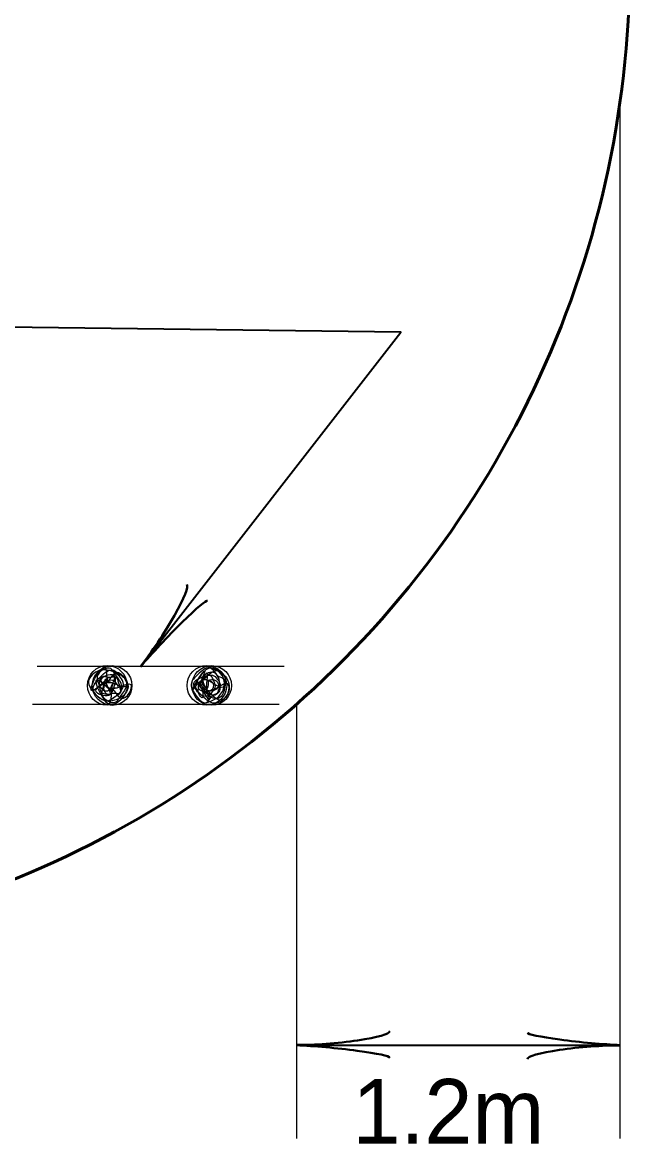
# Model space of a CAD drawing. Extents: x -198 to 658, y -402 to 142.
# Drawn here: x 390.19 to 412.76, y -116.61 to -74.95 of the extents above; entities that cross this region are included whole.
import ezdxf
from ezdxf.enums import TextEntityAlignment as Align

# ---------------------------------------------------------------- set-up
doc = ezdxf.new("R2010")
doc.units = 0
doc.header["$LTSCALE"] = 0.96
doc.layers.add('1', color=7, linetype='Continuous', lineweight=35)
doc.layers.add('4', color=7, linetype='Continuous', lineweight=25)

msp = doc.modelspace()

# ---------------------------------------------------------------- linework, layer by layer
at = {"layer": '1', "lineweight": 25}
for p, q in [((412.4134, -116.4304), (412.4134, -77.8663)), ((399.9154, -98.8829), (390.7354, -98.883)), ((399.736, -100.298), (390.556, -100.2979)), ((400.3925, -116.4304), (400.3925, -100.2786))]:
    msp.add_line(p, q, dxfattribs=at)
at = {"layer": '1'}
msp.add_line((400.3925, -112.9574), (412.4134, -112.9574), dxfattribs=at)
msp.add_lwpolyline([(394.5867, -98.883), (404.2583, -86.4576), (389.5755, -86.274)], dxfattribs=at)
at = {"layer": '1', "lineweight": 53}
msp.add_arc((376.0959, -72.8171), 36.6668, 269.84467, 11.96498, dxfattribs=at)
at = {"layer": '1', "lineweight": 40}
for centre, major_axis, ratio, start_param, end_param in [((395.1294, -97.646), (-1.1683, -1.8061), 0.122415, 0.8963533, 3.1415927), ((395.613, -97.9779), (-1.461, -1.5338), 0.07063, 3.1407148, 5.41811), ((401.7019, -112.6258), (-2.1428, -0.1874), 0.122415, 0.8963533, 3.1415927), ((411.0688, -112.7035), (2.1077, -0.2108), 0.07063, 3.1407148, 5.41811), ((401.7371, -113.2113), (-2.1077, 0.2108), 0.07063, 3.1407148, 5.41811), ((411.104, -113.289), (2.1428, 0.1874), 0.122415, 0.8963533, 3.1415927)]:
    msp.add_ellipse(centre, major_axis=major_axis, ratio=ratio, start_param=start_param, end_param=end_param, dxfattribs=at)
at = {"layer": '1', "lineweight": 25}
for points in [[(393.4, -100.154), (393.76, -99.902), (393.94, -99.542), (393.832, -99.29), (393.436, -99.038), (393.04, -99.038), (392.6439, -99.434), (392.896, -99.902), (393.4, -100.154), (393.616, -100.0099), (393.796, -99.902), (393.868, -99.578), (393.616, -99.146), (393.472, -98.966), (392.968, -99.254), (393.04, -99.614), (393.112, -99.83), (393.256, -99.902), (393.472, -99.902), (393.58, -99.686), (393.616, -99.29), (393.364, -99.29), (393.184, -99.254), (393.04, -99.47), (393.292, -99.794), (393.508, -99.65), (393.5439, -99.506), (393.292, -99.47), (393.328, -99.3979), (392.788, -99.794), (393.256, -98.93), (393.3641, -99.434), (393.6881, -99.11), (394.048, -99.614), (393.292, -99.47), (393.436, -99.938), (392.932, -99.83), (393.292, -99.47)], [(393.5794, -99.0269), (393.9394, -99.2789), (394.1194, -99.6389), (394.0114, -99.8909), (393.6154, -100.1429), (393.2194, -100.1429), (392.8233, -99.7469), (393.0754, -99.2789), (393.5794, -99.0269), (393.7954, -99.171), (393.9754, -99.2789), (394.0474, -99.6029), (393.7954, -100.0349), (393.6514, -100.2149), (393.1474, -99.9269), (393.2194, -99.5669), (393.2914, -99.3509), (393.4354, -99.2789), (393.6514, -99.2789), (393.7594, -99.4949), (393.7954, -99.8909), (393.5434, -99.8909), (393.3634, -99.9269), (393.2194, -99.7109), (393.4714, -99.3869), (393.6874, -99.5309), (393.7233, -99.6749), (393.4714, -99.7109), (393.5074, -99.783), (392.9674, -99.3869), (393.4354, -100.2509), (393.5435, -99.7469), (393.8675, -100.0709), (394.2274, -99.5669), (393.4714, -99.7109), (393.6154, -99.2429), (393.1114, -99.3509), (393.4714, -99.7109)], [(397.036, -100.226), (397.432, -100.046), (397.684, -99.65), (397.612, -99.218), (397.144, -98.93), (396.712, -99.1821), (396.46, -99.542), (396.532, -99.794), (397.036, -100.226), (397.288, -99.938), (397.504, -99.83), (397.54, -99.614), (397.2879, -99.11), (397.036, -99.146), (396.856, -99.29), (396.568, -99.47), (396.784, -99.902), (397.072, -99.9739), (397.252, -99.83), (397.36, -99.614), (397.288, -99.398), (397.216, -99.254), (396.856, -99.362), (396.928, -99.614), (396.928, -99.758), (397.216, -99.758), (397.288, -99.542), (396.892, -99.398), (396.82, -99.434), (396.496, -99.758), (396.964, -99.074), (396.856, -99.398), (397.396, -99.038), (397.648, -99.65), (396.892, -99.398), (396.856, -100.046), (396.748, -99.902), (396.892, -99.398)], [(397.2154, -98.9549), (397.6114, -99.1349), (397.8634, -99.5309), (397.7914, -99.9629), (397.3234, -100.2509), (396.8914, -99.9988), (396.6394, -99.6389), (396.7114, -99.3869), (397.2154, -98.9549), (397.4674, -99.2429), (397.6834, -99.3509), (397.7194, -99.5669), (397.4673, -100.0709), (397.2154, -100.0349), (397.0354, -99.8909), (396.7474, -99.7109), (396.9634, -99.2789), (397.2514, -99.207), (397.4314, -99.3509), (397.5394, -99.5669), (397.4674, -99.7829), (397.3954, -99.9269), (397.0354, -99.8189), (397.1074, -99.5669), (397.1074, -99.4229), (397.3954, -99.4229), (397.4674, -99.6389), (397.0714, -99.7829), (396.9994, -99.7469), (396.6754, -99.4229), (397.1434, -100.1069), (397.0354, -99.7829), (397.5754, -100.1429), (397.8274, -99.5309), (397.0714, -99.7829), (397.0354, -99.1349), (396.9274, -99.2789), (397.0714, -99.7829)]]:
    msp.add_spline(points, degree=3, dxfattribs=at)
at = {"layer": '4'}
for centre in [(393.3422, -99.5895), (393.5216, -99.5914), (397.0444, -99.5898), (397.2238, -99.5911)]:
    msp.add_circle(centre, 0.738, dxfattribs=at)

# ---------------------------------------------------------------- texts
at = {"layer": '1'}
msp.add_text('1.2m', height=2.4, dxfattribs=at).set_placement((406.026, -116.6134), align=Align.CENTER)

doc.saveas('drawing.dxf')
